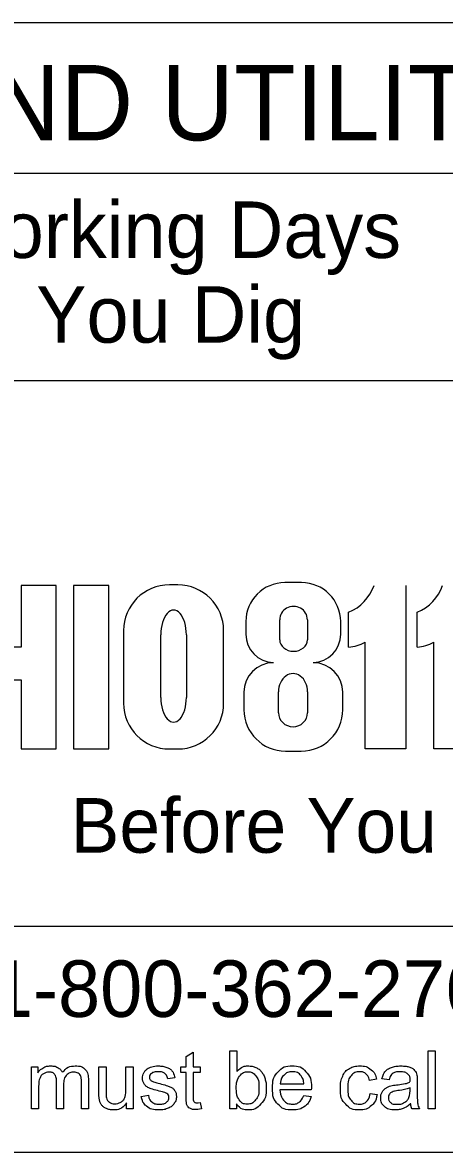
# Model space of a CAD drawing. Extents: x -37878.7 to -37844.7, y -19791.4 to -19769.4.
# Drawn here: x -37874.124 to -37873.006, y -19786.958 to -19783.958 of the extents above; entities that cross this region are included whole.
import ezdxf

# ---------------------------------------------------------------- set-up
doc = ezdxf.new("R2010")
doc.units = 0
doc.layers.add('SH_Data', color=7, linetype='Continuous')

msp = doc.modelspace()

# ---------------------------------------------------------------- linework, layer by layer
at = {"layer": 'SH_Data'}
for p, q in [((-37876.1278, -19783.9577), (-37871.3778, -19783.9577)), ((-37876.1278, -19784.3577), (-37871.3778, -19784.3577)), ((-37876.1278, -19784.9077), (-37871.3778, -19784.9077)), ((-37873.7129, -19785.4507), (-37873.7353, -19785.4507)), ((-37873.3846, -19785.4447), (-37873.429, -19785.4447)), ((-37873.1084, -19785.452), (-37873.1084, -19785.8865)), ((-37873.26, -19785.6159), (-37873.26, -19785.5233)), ((-37873.0781, -19785.6159), (-37873.0781, -19785.5233)), ((-37873.5326, -19785.5483), (-37873.5326, -19785.5813)), ((-37873.4428, -19785.5968), (-37873.4428, -19785.5434)), ((-37873.3693, -19785.5434), (-37873.3693, -19785.5968)), ((-37873.2809, -19785.5813), (-37873.2809, -19785.5483)), ((-37873.8568, -19785.5722), (-37873.8568, -19785.765)), ((-37873.7578, -19785.7496), (-37873.7578, -19785.5834)), ((-37873.6902, -19785.5834), (-37873.6902, -19785.7496)), ((-37873.5914, -19785.765), (-37873.5914, -19785.5722)), ((-37873.2161, -19785.8865), (-37873.2161, -19785.6032)), ((-37873.0342, -19785.8865), (-37873.0342, -19785.6032)), ((-37873.5377, -19785.736), (-37873.5377, -19785.7822)), ((-37873.446, -19785.7903), (-37873.446, -19785.7348)), ((-37873.3688, -19785.7348), (-37873.3688, -19785.7903)), ((-37873.2754, -19785.7822), (-37873.2754, -19785.736)), ((-37873.7353, -19785.8865), (-37873.7129, -19785.8865)), ((-37873.4277, -19785.8922), (-37873.3854, -19785.8922)), ((-37873.1084, -19785.8865), (-37873.2161, -19785.8865)), ((-37872.9265, -19785.8865), (-37873.0342, -19785.8865)), ((-37871.3778, -19786.3577), (-37876.1278, -19786.3577)), ((-37871.3778, -19786.9577), (-37876.1278, -19786.9577))]:
    msp.add_line(p, q, dxfattribs=at)
for points in [[(-37874.1973, -19785.7028), (-37874.1281, -19785.7028), (-37874.1281, -19785.8865), (-37874.0358, -19785.8865), (-37874.0358, -19785.452), (-37874.1281, -19785.452), (-37874.1281, -19785.6159), (-37874.1973, -19785.6159), (-37874.1973, -19785.452)], [(-37873.9896, -19785.8865), (-37873.8962, -19785.8865), (-37873.8962, -19785.452), (-37873.9896, -19785.452), (-37873.9896, -19785.8865)], [(-37873.4591, -19785.6574), (-37873.4591, -19785.6574)], [(-37873.354, -19785.6574), (-37873.354, -19785.6573)], [(-37873.691, -19786.8097), (-37873.691, -19786.7454), (-37873.705, -19786.7454), (-37873.705, -19786.7307), (-37873.691, -19786.7307), (-37873.691, -19786.7031), (-37873.6721, -19786.6917), (-37873.6721, -19786.7307), (-37873.6532, -19786.7307), (-37873.6532, -19786.7454), (-37873.6721, -19786.7454), (-37873.6721, -19786.8108)], [(-37873.5575, -19786.8423), (-37873.575, -19786.8423), (-37873.575, -19786.6883), (-37873.5561, -19786.6883), (-37873.5561, -19786.7432)], [(-37873.0492, -19786.8423), (-37873.0492, -19786.6883), (-37873.0303, -19786.6883), (-37873.0303, -19786.8423), (-37873.0492, -19786.8423)], [(-37874.1009, -19786.8423), (-37874.1009, -19786.7307), (-37874.084, -19786.7307), (-37874.084, -19786.7465)], [(-37873.9221, -19786.7998), (-37873.9221, -19786.7307), (-37873.9032, -19786.7307), (-37873.9032, -19786.7926)], [(-37873.8506, -19786.7905), (-37873.8506, -19786.7307), (-37873.8317, -19786.7307), (-37873.8317, -19786.8423), (-37873.8486, -19786.8423)], [(-37873.721, -19786.7596), (-37873.7396, -19786.762)], [(-37873.1863, -19786.7636), (-37873.2047, -19786.7664)], [(-37873.1529, -19786.7651), (-37873.1715, -19786.7626)], [(-37874.082, -19786.7845), (-37874.082, -19786.8423), (-37874.1009, -19786.8423)], [(-37874.0157, -19786.7775), (-37874.0157, -19786.8423), (-37874.0346, -19786.8423), (-37874.0346, -19786.7699)], [(-37873.9496, -19786.7657), (-37873.9496, -19786.8423), (-37873.9685, -19786.8423), (-37873.9685, -19786.7721)], [(-37873.3589, -19786.7914), (-37873.4422, -19786.7914)], [(-37873.4411, -19786.7759), (-37873.3788, -19786.7759)], [(-37873.0972, -19786.7933), (-37873.0971, -19786.7863)], [(-37873.078, -19786.7704), (-37873.078, -19786.7956)], [(-37873.8097, -19786.809), (-37873.791, -19786.8061)], [(-37873.379, -19786.8063), (-37873.3594, -19786.8088)], [(-37873.2031, -19786.8015), (-37873.1845, -19786.8039)], [(-37873.8486, -19786.8423), (-37873.8486, -19786.8258)], [(-37873.6532, -19786.8255), (-37873.6505, -19786.8422)], [(-37873.5575, -19786.8284), (-37873.5575, -19786.8423)], [(-37873.0721, -19786.8423), (-37873.0918, -19786.8423)]]:
    msp.add_lwpolyline(points, dxfattribs=at)
for centre, radius, start, end in [((-37873.7353, -19785.5722), 0.1215, 90, 180), ((-37873.7129, -19785.5722), 0.1215, 0, 90), ((-37873.429, -19785.5483), 0.1036, 90, 180), ((-37873.3846, -19785.5483), 0.1036, 0, 90), ((-37873.3061, -19785.4124), 0.1202, 292.5572, 340.7355), ((-37873.1242, -19785.4124), 0.1202, 292.5572, 340.7355), ((-37873.4566, -19785.5813), 0.076, 180, 268.1442), ((-37873.357, -19785.5813), 0.076, 272.2058, 0), ((-37873.2708, -19785.4962), 0.1202, 275.1733, 297.0931), ((-37873.0889, -19785.4962), 0.1202, 275.1733, 297.0931), ((-37873.4591, -19785.736), 0.0786, 90, 180), ((-37873.354, -19785.736), 0.0786, 0, 90), ((-37873.7353, -19785.765), 0.1215, 180, 270), ((-37873.7129, -19785.765), 0.1215, 270, 0), ((-37873.4277, -19785.7822), 0.1099, 180, 270), ((-37873.3854, -19785.7822), 0.1099, 270, 0)]:
    msp.add_arc(centre, radius, start, end, dxfattribs=at)
for centre, major_axis, ratio, start_param, end_param in [((-37873.724, -19785.5834), (0, 0.0657), 0.514403, 4.712389, 7.853982), ((-37873.406, -19785.5434), (0.0368, 0), 0.969373, 0, 3.141593), ((-37873.406, -19785.5968), (0.0368, 0), 0.818453, 3.141593, 6.283185), ((-37873.4074, -19785.7348), (0, 0.0486), 0.794529, 4.712389, 7.853982), ((-37873.724, -19785.7496), (0, 0.0657), 0.514403, 1.570796, 4.712389), ((-37873.4074, -19785.7903), (0.0386, 0), 0.959837, 3.141593, 6.283185)]:
    msp.add_ellipse(centre, major_axis=major_axis, ratio=ratio, start_param=start_param, end_param=end_param, dxfattribs=at)
for points, degree in [([(-37874.084, -19786.7465), (-37874.0787, -19786.7382), (-37874.07, -19786.7332), (-37874.0613, -19786.7282), (-37874.0502, -19786.7282), (-37874.0378, -19786.7282), (-37874.0298, -19786.7334), (-37874.0219, -19786.7386), (-37874.0186, -19786.7478), (-37874.0054, -19786.7282), (-37873.9841, -19786.7282), (-37873.9675, -19786.7282), (-37873.9585, -19786.7374), (-37873.9496, -19786.7466), (-37873.9496, -19786.7657)], 3), ([(-37873.791, -19786.8061), (-37873.7894, -19786.8173), (-37873.7822, -19786.8233), (-37873.775, -19786.8293), (-37873.762, -19786.8293), (-37873.749, -19786.8293), (-37873.7426, -19786.824), (-37873.7363, -19786.8187), (-37873.7363, -19786.8115), (-37873.7363, -19786.8051), (-37873.7419, -19786.8014), (-37873.7458, -19786.7989), (-37873.7613, -19786.795), (-37873.7821, -19786.7897), (-37873.7901, -19786.7859), (-37873.7982, -19786.7821), (-37873.8023, -19786.7753), (-37873.8065, -19786.7685), (-37873.8065, -19786.7604), (-37873.8065, -19786.7529), (-37873.8031, -19786.7466), (-37873.7997, -19786.7402), (-37873.7938, -19786.736), (-37873.7893, -19786.7327), (-37873.7817, -19786.7305), (-37873.7741, -19786.7282), (-37873.7653, -19786.7282), (-37873.7522, -19786.7282), (-37873.7422, -19786.732), (-37873.7323, -19786.7358), (-37873.7276, -19786.7423), (-37873.7228, -19786.7487), (-37873.721, -19786.7596)], 3), ([(-37873.5561, -19786.7432), (-37873.5442, -19786.7282), (-37873.5256, -19786.7282), (-37873.5153, -19786.7282), (-37873.5061, -19786.7324), (-37873.4969, -19786.7365), (-37873.491, -19786.744), (-37873.485, -19786.7515), (-37873.4817, -19786.7621), (-37873.4783, -19786.7728), (-37873.4783, -19786.7848), (-37873.4783, -19786.8135), (-37873.4925, -19786.8291), (-37873.5067, -19786.8448), (-37873.5265, -19786.8448), (-37873.5463, -19786.8448), (-37873.5575, -19786.8284)], 3), ([(-37873.3594, -19786.8088), (-37873.3641, -19786.8259), (-37873.3766, -19786.8353), (-37873.3891, -19786.8448), (-37873.4085, -19786.8448), (-37873.433, -19786.8448), (-37873.4473, -19786.8297), (-37873.4616, -19786.8147), (-37873.4616, -19786.7875), (-37873.4616, -19786.7593), (-37873.4471, -19786.7438), (-37873.4327, -19786.7282), (-37873.4095, -19786.7282), (-37873.3872, -19786.7282), (-37873.373, -19786.7435), (-37873.3588, -19786.7587), (-37873.3588, -19786.7863), (-37873.3588, -19786.788), (-37873.3589, -19786.7914)], 3), ([(-37873.1845, -19786.8039), (-37873.1876, -19786.8231), (-37873.2001, -19786.8339), (-37873.2127, -19786.8448), (-37873.231, -19786.8448), (-37873.2539, -19786.8448), (-37873.2678, -19786.8298), (-37873.2817, -19786.8149), (-37873.2817, -19786.7869), (-37873.2817, -19786.7689), (-37873.2757, -19786.7553), (-37873.2697, -19786.7418), (-37873.2575, -19786.735), (-37873.2452, -19786.7282), (-37873.2308, -19786.7282), (-37873.2126, -19786.7282), (-37873.2011, -19786.7374), (-37873.1895, -19786.7466), (-37873.1863, -19786.7636)], 3), ([(-37873.1715, -19786.7626), (-37873.169, -19786.7507), (-37873.1632, -19786.7434), (-37873.1574, -19786.7361), (-37873.1465, -19786.7322), (-37873.1356, -19786.7282), (-37873.1212, -19786.7282), (-37873.1069, -19786.7282), (-37873.098, -19786.7316), (-37873.0891, -19786.735), (-37873.0849, -19786.7401), (-37873.0807, -19786.7452), (-37873.079, -19786.7529), (-37873.078, -19786.7578), (-37873.078, -19786.7704)], 3), ([(-37874.0346, -19786.7699), (-37874.0346, -19786.7573), (-37874.0392, -19786.751), (-37874.0438, -19786.7447), (-37874.0543, -19786.7447), (-37874.0623, -19786.7447), (-37874.0691, -19786.7489), (-37874.0759, -19786.7531), (-37874.079, -19786.7612), (-37874.082, -19786.7692), (-37874.082, -19786.7845)], 3), ([(-37873.9685, -19786.7721), (-37873.9685, -19786.7607), (-37873.9703, -19786.7557), (-37873.9722, -19786.7508), (-37873.977, -19786.7477), (-37873.9818, -19786.7447), (-37873.9884, -19786.7447), (-37874.0001, -19786.7447), (-37874.0079, -19786.7525), (-37874.0157, -19786.7603), (-37874.0157, -19786.7775)], 3), ([(-37873.7396, -19786.762), (-37873.7409, -19786.7534), (-37873.7469, -19786.7486), (-37873.7529, -19786.7437), (-37873.764, -19786.7437), (-37873.777, -19786.7437), (-37873.7826, -19786.748), (-37873.7882, -19786.7524), (-37873.7882, -19786.7581), (-37873.7882, -19786.7618), (-37873.7859, -19786.7648), (-37873.7836, -19786.7678), (-37873.7786, -19786.7698), (-37873.7758, -19786.7709), (-37873.7619, -19786.7747), (-37873.7418, -19786.78), (-37873.7338, -19786.7834), (-37873.7259, -19786.7868), (-37873.7214, -19786.7934), (-37873.7168, -19786.7999), (-37873.7168, -19786.8095), (-37873.7168, -19786.819), (-37873.7223, -19786.8273), (-37873.7279, -19786.8357), (-37873.7383, -19786.8402), (-37873.7487, -19786.8448), (-37873.7619, -19786.8448), (-37873.7837, -19786.8448), (-37873.7951, -19786.8358), (-37873.8065, -19786.8267), (-37873.8097, -19786.809)], 3), ([(-37873.5578, -19786.7857), (-37873.5578, -19786.8057), (-37873.5523, -19786.8147), (-37873.5434, -19786.8293), (-37873.5282, -19786.8293), (-37873.5158, -19786.8293), (-37873.5068, -19786.8185), (-37873.4978, -19786.8077), (-37873.4978, -19786.7864), (-37873.4978, -19786.7645), (-37873.5064, -19786.7541), (-37873.5151, -19786.7437), (-37873.5274, -19786.7437), (-37873.5397, -19786.7437), (-37873.5488, -19786.7545), (-37873.5578, -19786.7653), (-37873.5578, -19786.7857)], 3), ([(-37873.3788, -19786.7759), (-37873.38, -19786.7618), (-37873.3859, -19786.7547), (-37873.395, -19786.7437), (-37873.4094, -19786.7437), (-37873.4224, -19786.7437), (-37873.4313, -19786.7525), (-37873.4402, -19786.7612), (-37873.4411, -19786.7759)], 3), ([(-37873.2047, -19786.7664), (-37873.2073, -19786.7551), (-37873.214, -19786.7494), (-37873.2207, -19786.7437), (-37873.2301, -19786.7437), (-37873.2444, -19786.7437), (-37873.2533, -19786.754), (-37873.2622, -19786.7642), (-37873.2622, -19786.7864), (-37873.2622, -19786.8089), (-37873.2536, -19786.8191), (-37873.245, -19786.8293), (-37873.2311, -19786.8293), (-37873.22, -19786.8293), (-37873.2125, -19786.8225), (-37873.2051, -19786.8156), (-37873.2031, -19786.8015)], 3), ([(-37873.0955, -19786.8286), (-37873.1061, -19786.8375), (-37873.1158, -19786.8411), (-37873.1255, -19786.8448), (-37873.1366, -19786.8448), (-37873.155, -19786.8448), (-37873.1649, -19786.8358), (-37873.1748, -19786.8268), (-37873.1748, -19786.8129), (-37873.1748, -19786.8047), (-37873.171, -19786.7979), (-37873.1673, -19786.7912), (-37873.1613, -19786.7871), (-37873.1552, -19786.783), (-37873.1477, -19786.7809), (-37873.1421, -19786.7794), (-37873.1309, -19786.7781), (-37873.108, -19786.7753), (-37873.0972, -19786.7715), (-37873.0971, -19786.7676), (-37873.0971, -19786.7666), (-37873.0971, -19786.755), (-37873.1024, -19786.7503), (-37873.1096, -19786.7438), (-37873.1239, -19786.7438), (-37873.1372, -19786.7438), (-37873.1436, -19786.7485), (-37873.1499, -19786.7532), (-37873.1529, -19786.7651)], 3), ([(-37873.9032, -19786.7926), (-37873.9032, -19786.8074), (-37873.9021, -19786.8125), (-37873.9003, -19786.82), (-37873.8945, -19786.8242), (-37873.8887, -19786.8285), (-37873.8802, -19786.8285), (-37873.8717, -19786.8285), (-37873.8643, -19786.8241), (-37873.8568, -19786.8198), (-37873.8537, -19786.8122), (-37873.8506, -19786.8047), (-37873.8506, -19786.7905)], 3), ([(-37873.4422, -19786.7914), (-37873.4411, -19786.8098), (-37873.4317, -19786.8195), (-37873.4224, -19786.8293), (-37873.4084, -19786.8293), (-37873.398, -19786.8293), (-37873.3906, -19786.8238), (-37873.3833, -19786.8183), (-37873.379, -19786.8063)], 3), ([(-37873.0971, -19786.7863), (-37873.1074, -19786.7905), (-37873.128, -19786.7935), (-37873.1396, -19786.7952), (-37873.1445, -19786.7973), (-37873.1493, -19786.7994), (-37873.1519, -19786.8034), (-37873.1546, -19786.8074), (-37873.1546, -19786.8124), (-37873.1546, -19786.8199), (-37873.1489, -19786.825), (-37873.1431, -19786.83), (-37873.1321, -19786.83), (-37873.1212, -19786.83), (-37873.1127, -19786.8252), (-37873.1042, -19786.8204), (-37873.1002, -19786.8122), (-37873.0972, -19786.8057), (-37873.0972, -19786.7933)], 3), ([(-37873.8486, -19786.8258), (-37873.8617, -19786.8448), (-37873.884, -19786.8448), (-37873.8939, -19786.8448), (-37873.9024, -19786.841), (-37873.911, -19786.8372), (-37873.9151, -19786.8315), (-37873.9193, -19786.8258), (-37873.921, -19786.8175), (-37873.9221, -19786.8119), (-37873.9221, -19786.7998)], 3), ([(-37873.6505, -19786.8422), (-37873.6585, -19786.8439), (-37873.6648, -19786.8439), (-37873.675, -19786.8439), (-37873.6807, -19786.8406), (-37873.6864, -19786.8373), (-37873.6887, -19786.832), (-37873.691, -19786.8267), (-37873.691, -19786.8097)], 3), ([(-37873.6721, -19786.8108), (-37873.6721, -19786.8189), (-37873.6711, -19786.8212), (-37873.6701, -19786.8235), (-37873.6679, -19786.8249), (-37873.6656, -19786.8262), (-37873.6614, -19786.8262), (-37873.6583, -19786.8262), (-37873.6532, -19786.8255)], 3), ([(-37873.078, -19786.7956), (-37873.078, -19786.8219), (-37873.0768, -19786.8289), (-37873.0756, -19786.8359), (-37873.0721, -19786.8423)], 3), ([(-37873.0918, -19786.8423), (-37873.0947, -19786.8365), (-37873.0955, -19786.8286)], 2)]:
    msp.add_open_spline(points, degree=degree, dxfattribs=at)

# ---------------------------------------------------------------- texts
for s, height, p in [('UNDERGROUND UTILITIES', 0.2, (-37875.9709, -19784.2703)), ('Contact Two Working Days', 0.15, (-37875.551, -19784.5826)), ('Before You Dig', 0.15, (-37874.7355, -19784.8076)), ('Before You Dig', 0.1452, (-37873.9974, -19786.162)), ('OHIO811, 8-1-1, or 1-800-362-2764', 0.15, (-37875.9813, -19786.5979))]:
    msp.add_text(s, height=height, dxfattribs=at).set_placement(p)

doc.saveas('drawing.dxf')
